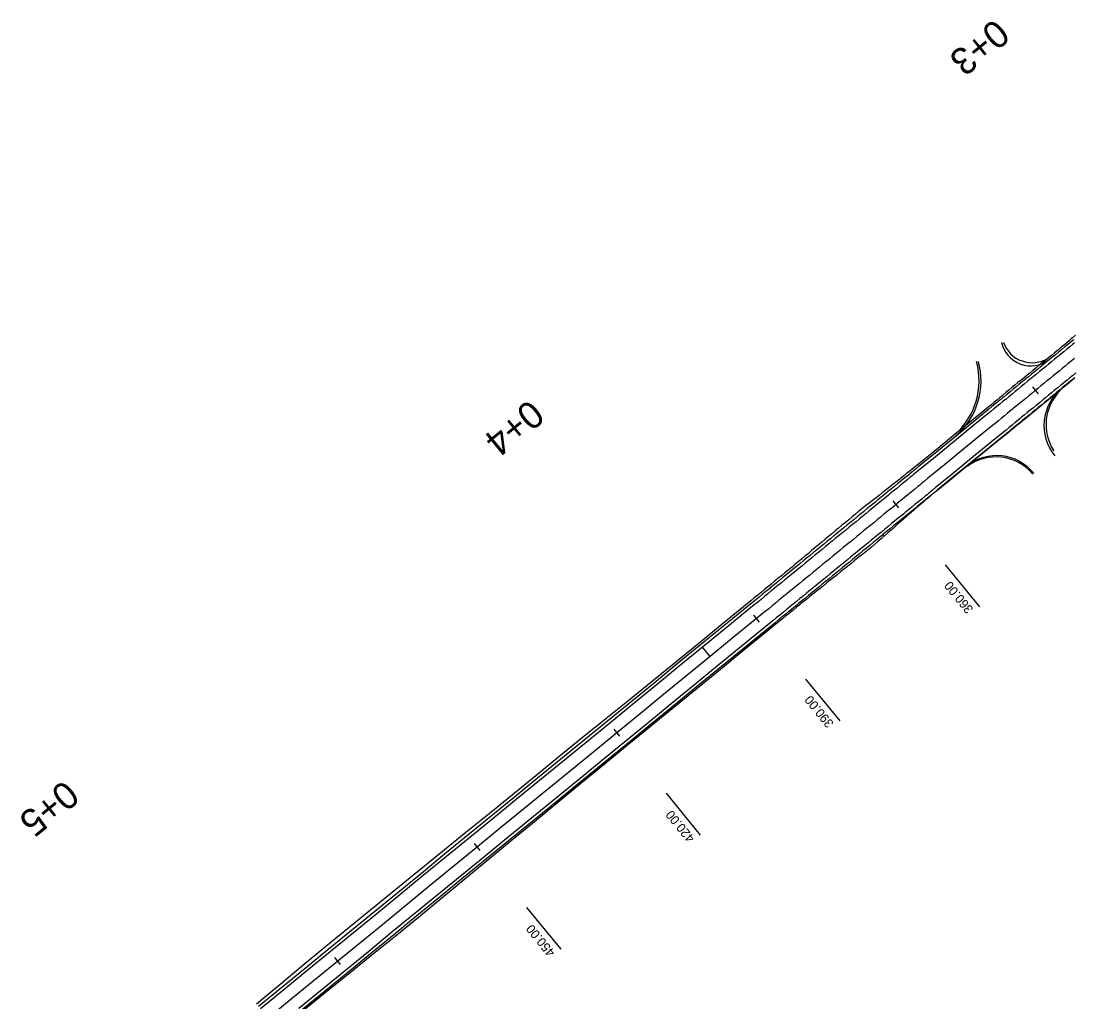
# Model space of a CAD drawing. Extents: x -550605 to -538780, y -1102367 to -1093705.
# Drawn here: x -546919.3 to -546744.3, y -1100912.8 to -1100749.7 of the extents above; entities that cross this region are included whole.
import ezdxf

# ---------------------------------------------------------------- set-up
doc = ezdxf.new("R2010")
doc.units = 0
for name, color, linetype in [('SIT - hrany vozovky', 7, 'Continuous'), ('SIT - oblouky - hrany', 7, 'Continuous'), ('SIT - oblouky - koruna', 7, 'Continuous'), ('SIT - osa cesty', 7, 'Continuous'), ('SIT - paty násypů', 7, 'Continuous'), ('SIT - staničení po 100m', 7, 'Continuous'), ('SIT - staničení po 30m', 7, 'Continuous')]:
    doc.layers.add(name, color=color, linetype=linetype)

msp = doc.modelspace()

# ---------------------------------------------------------------- linework, layer by layer
at = {"layer": 'SIT - hrany vozovky'}
for points in [[(-546744.11, -1100802.65), (-546744.32, -1100802.82), (-546744.62, -1100803.07), (-546745.12, -1100803.48), (-546745.63, -1100803.89), (-546746.13, -1100804.31), (-546746.64, -1100804.72), (-546747.14, -1100805.13), (-546747.65, -1100805.55), (-546748.16, -1100805.96), (-546748.19, -1100805.99), (-546748.66, -1100806.37), (-546749.17, -1100806.79), (-546749.67, -1100807.2), (-546750.18, -1100807.62), (-546750.68, -1100808.03), (-546751.19, -1100808.44), (-546751.7, -1100808.86), (-546752.06, -1100809.15), (-546752.2, -1100809.27), (-546752.71, -1100809.68), (-546753.21, -1100810.1), (-546753.72, -1100810.51), (-546754.22, -1100810.92), (-546754.73, -1100811.34), (-546755.23, -1100811.75), (-546755.74, -1100812.16), (-546755.93, -1100812.32), (-546756.25, -1100812.58), (-546756.75, -1100812.99), (-546757.26, -1100813.4), (-546757.76, -1100813.82), (-546758.27, -1100814.23), (-546759.8, -1100815.48), (-546763.67, -1100818.65), (-546767.54, -1100821.81), (-546769.98, -1100823.8), (-546770.54, -1100824.26), (-546771.11, -1100824.73), (-546771.41, -1100824.98), (-546771.67, -1100825.19), (-546772.23, -1100825.65), (-546772.8, -1100826.11), (-546773.36, -1100826.57), (-546773.93, -1100827.03), (-546774.49, -1100827.49), (-546775.06, -1100827.95), (-546775.28, -1100828.14), (-546775.62, -1100828.42), (-546776.18, -1100828.88), (-546776.75, -1100829.34), (-546777.31, -1100829.8), (-546777.88, -1100830.26), (-546778.44, -1100830.72), (-546779, -1100831.18), (-546779.15, -1100831.31), (-546779.57, -1100831.64), (-546780.13, -1100832.11), (-546780.7, -1100832.57), (-546781.26, -1100833.03), (-546781.83, -1100833.49), (-546782.39, -1100833.95), (-546782.95, -1100834.41), (-546783.03, -1100834.47), (-546783.52, -1100834.87), (-546784.08, -1100835.33), (-546784.65, -1100835.8), (-546785.21, -1100836.26), (-546785.77, -1100836.72), (-546786.34, -1100837.18), (-546786.9, -1100837.64), (-546786.9, -1100837.64), (-546787.47, -1100838.1), (-546788.03, -1100838.56), (-546788.59, -1100839.02), (-546789.16, -1100839.49), (-546789.72, -1100839.95), (-546790.29, -1100840.41), (-546790.77, -1100840.8), (-546790.85, -1100840.87), (-546791.42, -1100841.33), (-546791.98, -1100841.79), (-546792.54, -1100842.25), (-546793.11, -1100842.71), (-546793.67, -1100843.17), (-546794.24, -1100843.64), (-546794.64, -1100843.96), (-546794.8, -1100844.1), (-546795.36, -1100844.56), (-546795.93, -1100845.02), (-546796.49, -1100845.48), (-546797.06, -1100845.94), (-546797.62, -1100846.4), (-546798.51, -1100847.13), (-546802.38, -1100850.29), (-546806.25, -1100853.46), (-546810.12, -1100856.62), (-546813.99, -1100859.79), (-546817.86, -1100862.95), (-546821.73, -1100866.12), (-546825.61, -1100869.28), (-546829.48, -1100872.45), (-546833.35, -1100875.61), (-546837.22, -1100878.78), (-546841.09, -1100881.94), (-546844.96, -1100885.11), (-546848.83, -1100888.27), (-546852.7, -1100891.44), (-546856.57, -1100894.6), (-546860.44, -1100897.77), (-546864.31, -1100900.93), (-546868.19, -1100904.1), (-546872.06, -1100907.26), (-546875.93, -1100910.43), (-546879.8, -1100913.59)], [(-546744, -1100803.21), (-546744.3, -1100803.45), (-546744.81, -1100803.87), (-546745.31, -1100804.28), (-546745.82, -1100804.69), (-546746.32, -1100805.11), (-546746.83, -1100805.52), (-546747.33, -1100805.94), (-546747.84, -1100806.35), (-546747.87, -1100806.37), (-546748.34, -1100806.76), (-546748.85, -1100807.18), (-546749.36, -1100807.59), (-546749.86, -1100808), (-546750.37, -1100808.42), (-546750.87, -1100808.83), (-546751.38, -1100809.24), (-546751.74, -1100809.54), (-546751.88, -1100809.66), (-546752.39, -1100810.07), (-546752.9, -1100810.48), (-546753.4, -1100810.9), (-546753.91, -1100811.31), (-546754.41, -1100811.72), (-546754.92, -1100812.14), (-546755.42, -1100812.55), (-546755.61, -1100812.7), (-546755.93, -1100812.96), (-546756.44, -1100813.38), (-546756.94, -1100813.79), (-546757.45, -1100814.2), (-546757.95, -1100814.62), (-546759.48, -1100815.87), (-546763.35, -1100819.03), (-546767.23, -1100822.2), (-546769.66, -1100824.19), (-546770.23, -1100824.65), (-546770.79, -1100825.11), (-546771.1, -1100825.36), (-546771.35, -1100825.57), (-546771.92, -1100826.04), (-546772.48, -1100826.5), (-546773.05, -1100826.96), (-546773.61, -1100827.42), (-546774.17, -1100827.88), (-546774.74, -1100828.34), (-546774.97, -1100828.53), (-546775.3, -1100828.8), (-546775.87, -1100829.26), (-546776.43, -1100829.73), (-546777, -1100830.19), (-546777.56, -1100830.65), (-546778.12, -1100831.11), (-546778.69, -1100831.57), (-546778.84, -1100831.69), (-546779.25, -1100832.03), (-546779.82, -1100832.49), (-546780.38, -1100832.95), (-546780.94, -1100833.41), (-546781.51, -1100833.88), (-546782.07, -1100834.34), (-546782.64, -1100834.8), (-546782.71, -1100834.86), (-546783.2, -1100835.26), (-546783.77, -1100835.72), (-546784.33, -1100836.18), (-546784.89, -1100836.64), (-546785.46, -1100837.1), (-546786.02, -1100837.57), (-546786.58, -1100838.02), (-546786.59, -1100838.03), (-546787.15, -1100838.49), (-546787.71, -1100838.95), (-546788.28, -1100839.41), (-546788.84, -1100839.87), (-546789.41, -1100840.33), (-546789.97, -1100840.79), (-546790.45, -1100841.19), (-546790.53, -1100841.26), (-546791.1, -1100841.72), (-546791.66, -1100842.18), (-546792.23, -1100842.64), (-546792.79, -1100843.1), (-546793.36, -1100843.56), (-546793.92, -1100844.02), (-546794.32, -1100844.35), (-546794.48, -1100844.48), (-546795.05, -1100844.95), (-546795.61, -1100845.41), (-546796.18, -1100845.87), (-546796.74, -1100846.33), (-546797.3, -1100846.79), (-546798.19, -1100847.52), (-546802.06, -1100850.68), (-546805.93, -1100853.85), (-546809.81, -1100857.01), (-546813.68, -1100860.18), (-546817.55, -1100863.34), (-546821.42, -1100866.51), (-546825.29, -1100869.67), (-546829.16, -1100872.84), (-546833.03, -1100876), (-546836.9, -1100879.16), (-546840.77, -1100882.33), (-546844.64, -1100885.49), (-546848.51, -1100888.66), (-546852.39, -1100891.82), (-546856.26, -1100894.99), (-546860.13, -1100898.15), (-546864, -1100901.32), (-546867.87, -1100904.48), (-546871.74, -1100907.65), (-546875.61, -1100910.81), (-546879.48, -1100913.98)], [(-546743.79, -1100808.21), (-546744.3, -1100808.62), (-546744.8, -1100809.03), (-546745.31, -1100809.45), (-546745.34, -1100809.47), (-546745.81, -1100809.86), (-546746.32, -1100810.27), (-546746.82, -1100810.69), (-546747.33, -1100811.1), (-546747.84, -1100811.51), (-546748.34, -1100811.93), (-546748.85, -1100812.34), (-546749.21, -1100812.64), (-546749.35, -1100812.75), (-546749.86, -1100813.17), (-546750.36, -1100813.58), (-546750.87, -1100813.99), (-546751.38, -1100814.41), (-546751.88, -1100814.82), (-546752.39, -1100815.23), (-546752.89, -1100815.65), (-546753.08, -1100815.8), (-546753.4, -1100816.06), (-546753.9, -1100816.47), (-546754.41, -1100816.89), (-546754.91, -1100817.3), (-546755.42, -1100817.71), (-546756.95, -1100818.97), (-546760.82, -1100822.13), (-546764.69, -1100825.3), (-546767.13, -1100827.29), (-546767.69, -1100827.75), (-546768.26, -1100828.21), (-546768.56, -1100828.46), (-546768.82, -1100828.67), (-546769.39, -1100829.13), (-546769.95, -1100829.59), (-546770.51, -1100830.05), (-546771.08, -1100830.52), (-546771.64, -1100830.98), (-546772.21, -1100831.44), (-546772.44, -1100831.62), (-546772.77, -1100831.9), (-546773.34, -1100832.36), (-546773.9, -1100832.82), (-546774.46, -1100833.28), (-546775.03, -1100833.74), (-546775.59, -1100834.21), (-546776.16, -1100834.67), (-546776.31, -1100834.79), (-546776.72, -1100835.13), (-546777.28, -1100835.59), (-546777.85, -1100836.05), (-546778.41, -1100836.51), (-546778.98, -1100836.97), (-546779.54, -1100837.43), (-546780.11, -1100837.9), (-546780.18, -1100837.95), (-546780.67, -1100838.36), (-546781.23, -1100838.82), (-546781.8, -1100839.28), (-546782.36, -1100839.74), (-546782.93, -1100840.2), (-546783.49, -1100840.66), (-546784.05, -1100841.12), (-546784.05, -1100841.12), (-546784.62, -1100841.59), (-546785.18, -1100842.05), (-546785.75, -1100842.51), (-546786.31, -1100842.97), (-546786.87, -1100843.43), (-546787.44, -1100843.89), (-546787.92, -1100844.28), (-546788, -1100844.35), (-546788.57, -1100844.81), (-546789.13, -1100845.28), (-546789.7, -1100845.74), (-546790.26, -1100846.2), (-546790.82, -1100846.66), (-546791.39, -1100847.12), (-546791.79, -1100847.45), (-546791.95, -1100847.58), (-546792.52, -1100848.04), (-546793.08, -1100848.5), (-546793.64, -1100848.96), (-546794.21, -1100849.43), (-546794.77, -1100849.89), (-546795.66, -1100850.61), (-546799.53, -1100853.78), (-546803.4, -1100856.94), (-546807.27, -1100860.11), (-546811.14, -1100863.27), (-546815.02, -1100866.44), (-546818.89, -1100869.6), (-546822.76, -1100872.77), (-546826.63, -1100875.93), (-546830.5, -1100879.1), (-546834.37, -1100882.26), (-546838.24, -1100885.43), (-546842.11, -1100888.59), (-546845.98, -1100891.76), (-546849.85, -1100894.92), (-546853.72, -1100898.09), (-546857.6, -1100901.25), (-546861.47, -1100904.42), (-546865.34, -1100907.58), (-546869.21, -1100910.74), (-546873.08, -1100913.91)], [(-546743.98, -1100809.01), (-546744.49, -1100809.42), (-546744.99, -1100809.83), (-546745.02, -1100809.86), (-546745.5, -1100810.25), (-546746, -1100810.66), (-546746.51, -1100811.07), (-546747.01, -1100811.49), (-546747.52, -1100811.9), (-546748.02, -1100812.31), (-546748.53, -1100812.73), (-546748.89, -1100813.02), (-546749.04, -1100813.14), (-546749.54, -1100813.55), (-546750.05, -1100813.97), (-546750.55, -1100814.38), (-546751.06, -1100814.79), (-546751.56, -1100815.21), (-546752.07, -1100815.62), (-546752.58, -1100816.03), (-546752.76, -1100816.19), (-546753.08, -1100816.45), (-546753.59, -1100816.86), (-546754.09, -1100817.27), (-546754.6, -1100817.69), (-546755.1, -1100818.1), (-546756.64, -1100819.35), (-546760.51, -1100822.52), (-546764.38, -1100825.68), (-546766.81, -1100827.67), (-546767.38, -1100828.14), (-546767.94, -1100828.6), (-546768.25, -1100828.85), (-546768.51, -1100829.06), (-546769.07, -1100829.52), (-546769.63, -1100829.98), (-546770.2, -1100830.44), (-546770.76, -1100830.9), (-546771.33, -1100831.36), (-546771.89, -1100831.83), (-546772.12, -1100832.01), (-546772.45, -1100832.29), (-546773.02, -1100832.75), (-546773.58, -1100833.21), (-546774.15, -1100833.67), (-546774.71, -1100834.13), (-546775.28, -1100834.59), (-546775.84, -1100835.05), (-546775.99, -1100835.18), (-546776.4, -1100835.52), (-546776.97, -1100835.98), (-546777.53, -1100836.44), (-546778.1, -1100836.9), (-546778.66, -1100837.36), (-546779.22, -1100837.82), (-546779.79, -1100838.28), (-546779.86, -1100838.34), (-546780.35, -1100838.74), (-546780.92, -1100839.2), (-546781.48, -1100839.67), (-546782.05, -1100840.13), (-546782.61, -1100840.59), (-546783.17, -1100841.05), (-546783.73, -1100841.51), (-546783.74, -1100841.51), (-546784.3, -1100841.97), (-546784.87, -1100842.43), (-546785.43, -1100842.89), (-546785.99, -1100843.36), (-546786.56, -1100843.82), (-546787.12, -1100844.28), (-546787.6, -1100844.67), (-546787.69, -1100844.74), (-546788.25, -1100845.2), (-546788.81, -1100845.66), (-546789.38, -1100846.12), (-546789.94, -1100846.58), (-546790.51, -1100847.05), (-546791.07, -1100847.51), (-546791.47, -1100847.84), (-546791.64, -1100847.97), (-546792.2, -1100848.43), (-546792.76, -1100848.89), (-546793.33, -1100849.35), (-546793.89, -1100849.81), (-546794.46, -1100850.27), (-546795.34, -1100851), (-546799.22, -1100854.17), (-546803.09, -1100857.33), (-546806.96, -1100860.5), (-546810.83, -1100863.66), (-546814.7, -1100866.82), (-546818.57, -1100869.99), (-546822.44, -1100873.15), (-546826.31, -1100876.32), (-546830.18, -1100879.48), (-546834.05, -1100882.65), (-546837.92, -1100885.81), (-546841.8, -1100888.98), (-546845.67, -1100892.14), (-546849.54, -1100895.31), (-546853.41, -1100898.47), (-546857.28, -1100901.64), (-546861.15, -1100904.8), (-546865.02, -1100907.97), (-546868.89, -1100911.13), (-546872.76, -1100914.3)]]:
    msp.add_lwpolyline(points, dxfattribs=at)
at = {"layer": 'SIT - oblouky - hrany'}
for centre, radius, start, end in [((-546751.1, -1100801.51), 5, 198.9675, 302.3382), ((-546771.9, -1100809.5), 12, 311.7499, 15.4109), ((-546740.76, -1100816.8), 8, 135.0694, 212.9184), ((-546757.08, -1100830.18), 8, 40.0756, 126.7687)]:
    msp.add_arc(centre, radius, start, end, dxfattribs=at)
at = {"layer": 'SIT - oblouky - koruna'}
for centre, radius, start, end in [((-546751.28, -1100802.04), 5, 192.4418, 307.0568), ((-546771.57, -1100809.55), 12, 310.5519, 15.7057), ((-546741.1, -1100816.99), 8, 129.5012, 218.9364), ((-546756.98, -1100829.97), 8, 39.3111, 128.2654)]:
    msp.add_arc(centre, radius, start, end, dxfattribs=at)
at = {"layer": 'SIT - osa cesty'}
msp.add_lwpolyline([(-546744.05, -1100805.83), (-546744.55, -1100806.24), (-546745.06, -1100806.66), (-546745.56, -1100807.07), (-546746.07, -1100807.48), (-546746.57, -1100807.9), (-546746.6, -1100807.92), (-546747.08, -1100808.31), (-546747.58, -1100808.72), (-546748.09, -1100809.14), (-546748.6, -1100809.55), (-546749.1, -1100809.96), (-546749.61, -1100810.38), (-546750.11, -1100810.79), (-546750.48, -1100811.09), (-546750.62, -1100811.2), (-546751.12, -1100811.62), (-546751.63, -1100812.03), (-546752.14, -1100812.44), (-546752.64, -1100812.86), (-546753.15, -1100813.27), (-546753.65, -1100813.68), (-546754.16, -1100814.1), (-546754.35, -1100814.25), (-546754.66, -1100814.51), (-546755.17, -1100814.92), (-546755.67, -1100815.34), (-546756.18, -1100815.75), (-546756.69, -1100816.16), (-546758.22, -1100817.42), (-546762.09, -1100820.58), (-546765.96, -1100823.75), (-546768.4, -1100825.74), (-546768.96, -1100826.2), (-546769.52, -1100826.66), (-546769.83, -1100826.91), (-546770.09, -1100827.12), (-546770.65, -1100827.58), (-546771.22, -1100828.04), (-546771.78, -1100828.51), (-546772.34, -1100828.97), (-546772.91, -1100829.43), (-546773.47, -1100829.89), (-546773.7, -1100830.08), (-546774.04, -1100830.35), (-546774.6, -1100830.81), (-546775.17, -1100831.27), (-546775.73, -1100831.73), (-546776.29, -1100832.2), (-546776.86, -1100832.66), (-546777.42, -1100833.12), (-546777.57, -1100833.24), (-546777.99, -1100833.58), (-546778.55, -1100834.04), (-546779.11, -1100834.5), (-546779.68, -1100834.96), (-546780.24, -1100835.42), (-546780.81, -1100835.89), (-546781.37, -1100836.35), (-546781.44, -1100836.41), (-546781.94, -1100836.81), (-546782.5, -1100837.27), (-546783.06, -1100837.73), (-546783.63, -1100838.19), (-546784.19, -1100838.65), (-546784.76, -1100839.11), (-546785.31, -1100839.57), (-546785.32, -1100839.58), (-546785.88, -1100840.04), (-546786.45, -1100840.5), (-546787.01, -1100840.96), (-546787.58, -1100841.42), (-546788.14, -1100841.88), (-546788.7, -1100842.34), (-546789.18, -1100842.74), (-546789.27, -1100842.8), (-546789.83, -1100843.27), (-546790.4, -1100843.73), (-546790.96, -1100844.19), (-546791.53, -1100844.65), (-546792.09, -1100845.11), (-546792.65, -1100845.57), (-546793.06, -1100845.9), (-546793.22, -1100846.03), (-546793.78, -1100846.49), (-546794.35, -1100846.96), (-546794.91, -1100847.42), (-546795.47, -1100847.88), (-546796.04, -1100848.34), (-546796.93, -1100849.07), (-546800.8, -1100852.23), (-546804.67, -1100855.39), (-546808.54, -1100858.56), (-546812.41, -1100861.72), (-546816.28, -1100864.89), (-546820.15, -1100868.05), (-546824.02, -1100871.22), (-546827.89, -1100874.38), (-546831.76, -1100877.55), (-546835.64, -1100880.71), (-546839.51, -1100883.88), (-546843.38, -1100887.04), (-546847.25, -1100890.21), (-546851.12, -1100893.37), (-546854.99, -1100896.54), (-546858.86, -1100899.7), (-546862.73, -1100902.87), (-546866.6, -1100906.03), (-546870.47, -1100909.2), (-546874.34, -1100912.36), (-546878.22, -1100915.53)], dxfattribs=at)
at = {"layer": 'SIT - paty násypů'}
for points in [[(-546743.85, -1100801.94), (-546744.35, -1100802.36), (-546744.55, -1100802.54), (-546744.84, -1100802.8), (-546745.32, -1100803.23), (-546745.83, -1100803.65), (-546746.34, -1100804.06), (-546746.84, -1100804.47), (-546747.35, -1100804.88), (-546747.86, -1100805.29), (-546748.36, -1100805.71), (-546748.4, -1100805.73), (-546748.87, -1100806.12), (-546749.38, -1100806.53), (-546749.88, -1100806.94), (-546750.39, -1100807.36), (-546750.9, -1100807.77), (-546751.4, -1100808.18), (-546751.91, -1100808.59), (-546752.27, -1100808.89), (-546752.41, -1100809.01), (-546752.92, -1100809.42), (-546753.43, -1100809.83), (-546753.93, -1100810.25), (-546754.44, -1100810.66), (-546754.94, -1100811.08), (-546755.45, -1100811.49), (-546755.95, -1100811.9), (-546756.14, -1100812.06), (-546756.46, -1100812.32), (-546756.96, -1100812.73), (-546757.47, -1100813.15), (-546757.97, -1100813.56), (-546758.47, -1100813.98), (-546760, -1100815.24), (-546763.86, -1100818.41), (-546767.73, -1100821.58), (-546770.19, -1100823.54), (-546770.76, -1100824), (-546771.33, -1100824.45), (-546771.64, -1100824.7), (-546771.9, -1100824.91), (-546772.47, -1100825.36), (-546773.04, -1100825.81), (-546773.61, -1100826.26), (-546774.19, -1100826.72), (-546774.76, -1100827.17), (-546775.33, -1100827.62), (-546775.56, -1100827.8), (-546775.9, -1100828.07), (-546776.47, -1100828.52), (-546777.04, -1100828.98), (-546777.62, -1100829.42), (-546778.2, -1100829.86), (-546778.78, -1100830.3), (-546779.34, -1100830.77), (-546779.49, -1100830.89), (-546779.91, -1100831.23), (-546780.47, -1100831.7), (-546781.03, -1100832.16), (-546781.59, -1100832.63), (-546782.15, -1100833.09), (-546782.71, -1100833.55), (-546783.28, -1100834.02), (-546783.35, -1100834.08), (-546783.84, -1100834.48), (-546784.4, -1100834.95), (-546784.96, -1100835.41), (-546785.52, -1100835.87), (-546786.09, -1100836.34), (-546786.64, -1100836.8), (-546787.2, -1100837.27), (-546787.2, -1100837.27), (-546787.76, -1100837.75), (-546788.31, -1100838.22), (-546788.87, -1100838.69), (-546789.43, -1100839.16), (-546789.98, -1100839.63), (-546790.54, -1100840.09), (-546791.02, -1100840.49), (-546791.11, -1100840.56), (-546791.67, -1100841.02), (-546792.23, -1100841.48), (-546792.8, -1100841.94), (-546793.36, -1100842.4), (-546793.92, -1100842.87), (-546794.49, -1100843.33), (-546794.89, -1100843.66), (-546795.05, -1100843.79), (-546795.62, -1100844.25), (-546796.18, -1100844.71), (-546796.74, -1100845.17), (-546797.31, -1100845.63), (-546797.87, -1100846.09), (-546798.76, -1100846.82), (-546802.63, -1100849.99), (-546806.5, -1100853.16), (-546810.36, -1100856.33), (-546814.24, -1100859.49), (-546818.13, -1100862.63), (-546822.03, -1100865.76), (-546825.92, -1100868.9), (-546829.8, -1100872.05), (-546833.68, -1100875.2), (-546837.56, -1100878.36), (-546841.44, -1100881.52), (-546845.31, -1100884.67), (-546849.19, -1100887.83), (-546853.08, -1100890.98), (-546856.96, -1100894.12), (-546860.83, -1100897.3), (-546864.7, -1100900.46), (-546868.58, -1100903.62), (-546872.44, -1100906.79), (-546876.26, -1100910.01), (-546880.11, -1100913.21)], [(-546743.94, -1100809.05), (-546744.45, -1100809.47), (-546744.95, -1100809.88), (-546744.98, -1100809.91), (-546745.45, -1100810.3), (-546745.96, -1100810.71), (-546746.46, -1100811.13), (-546746.97, -1100811.54), (-546747.47, -1100811.96), (-546747.98, -1100812.37), (-546748.48, -1100812.79), (-546748.84, -1100813.08), (-546748.99, -1100813.2), (-546749.49, -1100813.61), (-546750, -1100814.03), (-546750.5, -1100814.44), (-546751.01, -1100814.85), (-546751.51, -1100815.27), (-546752.02, -1100815.68), (-546752.53, -1100816.09), (-546752.71, -1100816.25), (-546753.03, -1100816.51), (-546753.54, -1100816.92), (-546754.04, -1100817.33), (-546754.55, -1100817.75), (-546755.06, -1100818.16), (-546756.59, -1100819.41), (-546760.47, -1100822.56), (-546764.35, -1100825.72), (-546766.79, -1100827.7), (-546767.36, -1100828.16), (-546767.92, -1100828.62), (-546768.23, -1100828.87), (-546768.48, -1100829.09), (-546769.04, -1100829.56), (-546769.6, -1100830.03), (-546770.15, -1100830.5), (-546770.7, -1100830.98), (-546771.25, -1100831.46), (-546771.8, -1100831.94), (-546772.02, -1100832.13), (-546772.35, -1100832.42), (-546772.9, -1100832.9), (-546773.45, -1100833.38), (-546773.99, -1100833.86), (-546774.54, -1100834.34), (-546775.09, -1100834.82), (-546775.64, -1100835.3), (-546775.78, -1100835.43), (-546776.19, -1100835.78), (-546776.73, -1100836.26), (-546777.28, -1100836.74), (-546777.83, -1100837.22), (-546778.4, -1100837.68), (-546778.97, -1100838.13), (-546779.54, -1100838.58), (-546779.61, -1100838.64), (-546780.11, -1100839.04), (-546780.68, -1100839.49), (-546781.25, -1100839.95), (-546781.82, -1100840.4), (-546782.39, -1100840.86), (-546782.96, -1100841.32), (-546783.52, -1100841.77), (-546783.52, -1100841.77), (-546784.09, -1100842.23), (-546784.66, -1100842.68), (-546785.23, -1100843.14), (-546785.8, -1100843.6), (-546786.37, -1100844.05), (-546786.93, -1100844.51), (-546787.42, -1100844.9), (-546787.5, -1100844.97), (-546788.07, -1100845.42), (-546788.64, -1100845.88), (-546789.2, -1100846.34), (-546789.77, -1100846.8), (-546790.34, -1100847.25), (-546790.9, -1100847.71), (-546791.31, -1100848.04), (-546791.47, -1100848.17), (-546792.04, -1100848.63), (-546792.6, -1100849.09), (-546793.17, -1100849.55), (-546793.74, -1100850), (-546794.3, -1100850.46), (-546795.19, -1100851.19), (-546799.07, -1100854.34), (-546802.94, -1100857.51), (-546806.81, -1100860.67), (-546810.68, -1100863.84), (-546814.55, -1100867), (-546818.43, -1100870.17), (-546822.3, -1100873.32), (-546826.17, -1100876.49), (-546830.02, -1100879.68), (-546833.88, -1100882.86), (-546837.74, -1100886.04), (-546841.59, -1100889.22), (-546845.45, -1100892.41), (-546849.31, -1100895.59), (-546853.17, -1100898.77), (-546857.04, -1100901.94), (-546860.93, -1100905.07), (-546864.83, -1100908.21), (-546868.72, -1100911.34), (-546872.6, -1100914.49)]]:
    msp.add_lwpolyline(points, dxfattribs=at)
at = {"layer": 'SIT - staničení po 100m'}
msp.add_lwpolyline([(-546804.67, -1100855.39), (-546805.93, -1100853.85)], dxfattribs=at)
at = {"layer": 'SIT - staničení po 30m'}
for points in [[(-546750, -1100811.67), (-546750.95, -1100810.51)], [(-546773.23, -1100830.66), (-546774.18, -1100829.5)], [(-546759.78, -1100847.11), (-546765.47, -1100840.14)], [(-546796.45, -1100849.65), (-546797.4, -1100848.48)], [(-546783, -1100866.1), (-546788.7, -1100859.13)], [(-546819.68, -1100868.63), (-546820.63, -1100867.47)], [(-546806.23, -1100885.09), (-546811.92, -1100878.12)], [(-546842.9, -1100887.62), (-546843.85, -1100886.46)], [(-546829.45, -1100904.07), (-546835.15, -1100897.11)], [(-546866.13, -1100906.61), (-546867.08, -1100905.45)]]:
    msp.add_lwpolyline(points, dxfattribs=at)

# ---------------------------------------------------------------- texts
at = {"layer": 'SIT - staničení po 100m'}
for s, p in [('0+3', (-546757.25, -1100749.13)), ('0+4', (-546834.68, -1100812.44)), ('0+5', (-546912.08, -1100875.73))]:
    msp.add_text(s, height=4.5, rotation=219.269, dxfattribs=at).set_placement(p)
at = {"layer": 'SIT - staničení po 30m'}
for s, p in [('360.00', (-546760.77, -1100847.47)), ('390.00', (-546784, -1100866.46)), ('420.00', (-546807.13, -1100885.56)), ('450.00', (-546830.36, -1100904.55))]:
    msp.add_text(s, height=1.5, rotation=129.269, dxfattribs=at).set_placement(p)

doc.saveas('drawing.dxf')
